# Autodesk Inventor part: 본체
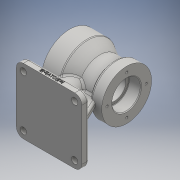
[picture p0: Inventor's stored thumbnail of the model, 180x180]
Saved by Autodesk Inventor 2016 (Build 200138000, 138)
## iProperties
Created: 2019-01
Part Number: 본체
Material: 일반
Document SubType Name: Modeling
Designer: USER
Density: 1 g/cm^3
Appearance: 기본값
Mass: 335.225 g
Surface Area: 600.378 cm^2
Volume: 335.225 cm^3
Author: USER
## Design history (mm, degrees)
sketch "스케치1"
  geometry: L1 (-40, 0)-(40, 0); L2 (-40, 0)-(-40, 40); L3 (-40, 40)-(-15, 40); L4 (2.321, 30)-(20.805, 30); L5 (20.805, 30)-(25, 35); L6 (25, 35)-(40, 35); L7 (40, 35)-(40, 0); L8 (-15, 40)-(2.321, 30); 2 further points
  constraints: 16 end point, 2 parallel, 2 perpendicular, 1 coincident, 1 horizontal, 1 midpoint, 1 vertical
  dimensions: "d0" = 80 distance of L1.start L1.end; "d1" = 80 diameter of L3 L1; "d2" = 70 diameter of L6 L1; "d3" = 60 diameter of L4 L1; "d4" = 25 distance of L2.end L3.end; "d5" = 15 distance of L6.end L5.end; "d7" = 30 deg angle of L8 L4; "d8" = 50 deg angle of L5 L4
revolve "회전1" sketch "스케치1" stored, may be unused: angle "d9" = 90 deg
node "작업 평면1"
sketch "스케치2"
  geometry: L1 (40, 40)-(40, -40) reference; L2 (35, 46)-(-57, 46); L3 (-57, 46)-(-57, -46); L4 (-57, -46)-(35, -46); L5 (35, -46)-(35, 46); L6 (35, 46)-(-57, -46); L7 (-57, 46)-(35, -46); 3 further points
  constraints: 12 end point, 3 midpoint, 2 parallel, 1 horizontal, 1 horizontal alignment, 1 perpendicular
  dimensions: "d88" = 5 distance between parallel lines of L5 L1; "d89" = 92 distance of L3.end L4.end; "d90" = 92 distance of L2.end L3.end
extrude "돌출1" join sketch "스케치2" distance "d13" = 10; taper "d14" = 0 deg
sketch "스케치5"
  geometry: C1 r 26 at (0, 0); 1 further point
  constraints: 1 centre point, 1 coincident
  dimensions: "d30" = 52 diameter of C1
extrude "돌출3" cut sketch "스케치5" distance "d31" = 20; taper "d32" = 0 deg
hole "구멍1" diameter "d35" = 32; stored, may be unused: countersink angle "d39" = 90 deg, drill point angle "d41" = 118 deg; dims "d33" = 10, "d34" = 10, "d36" = 6, "d37" = 40, "d38" = 17, "d40" = 76
chamfer "모따기1" distance "d42" = 1; stored, may be unused: second distance "d43" = 2, angle "d44" = 45 deg
sketch "스케치6"
  geometry: 2 further points
  dimensions: "d45" = 33 distance of point (0, 33) point (0, 0)
hole "구멍2" sketch "스케치6" at (0, 33) diameter "d46" = 3.242; stored, may be unused: countersink angle "d50" = 90 deg, drill point angle "d52" = 118 deg; dims "d47" = 9, "d48" = 40, "d49" = 17, "d51" = 11
sketch "스케치7"
  geometry: 2 further points
  constraints: 1 vertical alignment
  dimensions: "d56" = 27.5 distance of point (0, 27.5) point (0, 0)
hole "구멍3" sketch "스케치7" at (0, 27.5) diameter "d57" = 3.242; stored, may be unused: countersink angle "d61" = 90 deg, drill point angle "d63" = 118 deg; dims "d58" = 9, "d59" = 40, "d60" = 17, "d62" = 11
fillet "모깎기2" dims "d77" = 3
fillet "모깎기7" dims "d86" = 1
fillet "모깎기8" dims "d87" = 0.6
sketch "스케치9"
  geometry: L1 (-35, 46)-(-35, -46) reference; C1 r 16 at (-5, 0); 1 further point
  constraints: 1 centre point
  dimensions: "d91" = 30 distance from line of L1 C1.centre; "d92" = 32 diameter of C1
extrude "돌출4" join sketch "스케치9" stored distance "d93" = 20; taper "d94" = 0 deg
sketch "스케치10"
  geometry: L1 (57, -70)-(-35, -70) reference; L2 (47, -70)-(33.856, -41.813); L3 (57, -80)-(57, -70) reference; 1 further point
  constraints: 2 end point, 1 point on line
  dimensions: "d95" = 10 distance of L1.start L2.start; "d96" = 25 deg angle of L2 L3
feature "리브2" sketch "스케치10" dims "d97" = 1, "d98" = 10, "d99" = 0, "d100" = 0, "d101" = 1, "d102" = 1
fillet "모깎기9" dims "d103" = 10
fillet "모깎기10" dims "d104" = 3
fillet "모깎기11" dims "d105" = 3
fillet "모깎기12" dims "d106" = 3
hole "구멍5" diameter "d110" = 9; stored, may be unused: countersink angle "d114" = 90 deg, drill point angle "d116" = 118 deg; dims "d108" = 10, "d109" = 10, "d111" = 9, "d112" = 40, "d113" = 17, "d115" = 11
hole "구멍6" diameter "d119" = 9; stored, may be unused: countersink angle "d123" = 90 deg, drill point angle "d125" = 118 deg; dims "d117" = 10, "d118" = 10, "d120" = 9, "d121" = 40, "d122" = 17, "d124" = 11
fillet "모깎기14" dims "d126" = 3
sketch "스케치11"
  geometry: L1 (-10, 7)-(-10, 0) reference; L2 (0, 0)-(72, 0) reference; 2 further points
  constraints: 1 other
  dimensions: "d127" = 46 distance from line of L1 point (36, 4); "d128" = 4 distance from line of point (36, 4) L2
feature "엠보싱2" sketch "스케치11" dims "d129" = 0.5, "d130" = 0
node "솔리드1"
pattern_circular "원형 패턴1" dims angle "d54" = 360 deg
pattern_circular "원형 패턴2" dims angle "d65" = 360 deg
mirror "대칭3"
